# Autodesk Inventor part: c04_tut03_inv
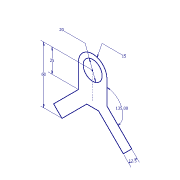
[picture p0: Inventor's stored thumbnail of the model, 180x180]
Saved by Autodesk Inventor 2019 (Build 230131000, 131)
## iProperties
Created: 2017-04
Part Number: c04_tut03_inv
Material: Generic
Document SubType Name: Modeling
Designer: CADCIM 00
Density: 1 g/cm^3
Appearance: Default
Author: CADCIM 00
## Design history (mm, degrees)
sketch "Sketch1"
  geometry: L1 (-6.25, -33.928)-(6.25, -33.928); L2 (6.25, -33.928)-(32.322, -60); L3 (32.322, -60)-(41.161, -51.161); L4 (41.161, -51.161)-(15, -25); L5 (15, -25)-(15, 0); L6 (-15, 0)-(-15, -25); L7 (-15, -25)-(-41.161, -51.161); L8 (-41.161, -51.161)-(-32.322, -60); L9 (-32.322, -60)-(-6.25, -33.928); L10 (0, 0)-(0, -28.219); C1 r 10 at (0, 0); A1 r 15 centre (0, 0) between (15, 0) and (-15, 0); 1 further point
  constraints: 20 end point, 5 perpendicular, 2 centre point, 2 coincident, 2 point on circle, 2 symmetric about line, 2 tangent, 1 concentric, 1 equal length, 1 horizontal, 1 parallel, 1 point on line, 1 vertical, 2 other
  dimensions: "d0" = 15 radius of A1; "d1" = 135 deg angle of L7 L6; "d2" = 12.5 distance of L7.end L8.end; "d3" = 60 vertical distance of L2.end L10.start; "d4" = 25 vertical distance of L10.start L4.end; "d5" = 20 diameter of C1
